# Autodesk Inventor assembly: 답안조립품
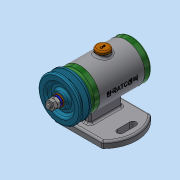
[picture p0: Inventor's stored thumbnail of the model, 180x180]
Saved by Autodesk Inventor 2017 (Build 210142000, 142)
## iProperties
Part Number: 답안조립품
Material: 일반
Document SubType Name: Assembly
Designer: user
Author: user
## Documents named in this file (14)
- C:\Users\user\Desktop\710906V1010\답안조립품.iam
- C:\Users\user\Desktop\710906V1010\본체.ipt
- C:\Users\user\Desktop\710906V1010\V벨트풀리.ipt
- C:\Users\user\Desktop\710906V1010\너트 M8.ipt
- C:\Users\user\Desktop\710906V1010\뒤커버.ipt
- C:\Users\user\Desktop\710906V1010\베어링 15x32x9.ipt
- C:\Users\user\Desktop\710906V1010\볼트 M4x12.ipt
- C:\Users\user\Desktop\710906V1010\스프링와셔 8.ipt
- C:\Users\user\Desktop\710906V1010\앞커버.ipt
- C:\Users\user\Desktop\710906V1010\오일 실 15x25x7.ipt
- C:\Users\user\Desktop\710906V1010\와셔 8x17.ipt
- C:\Users\user\Desktop\710906V1010\축.ipt
- C:\Users\user\Desktop\710906V1010\캡.ipt
- C:\Users\user\Desktop\710906V1010\키 3x3.ipt
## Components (1 placed, 1 different names)
1. V벨트풀리:1
